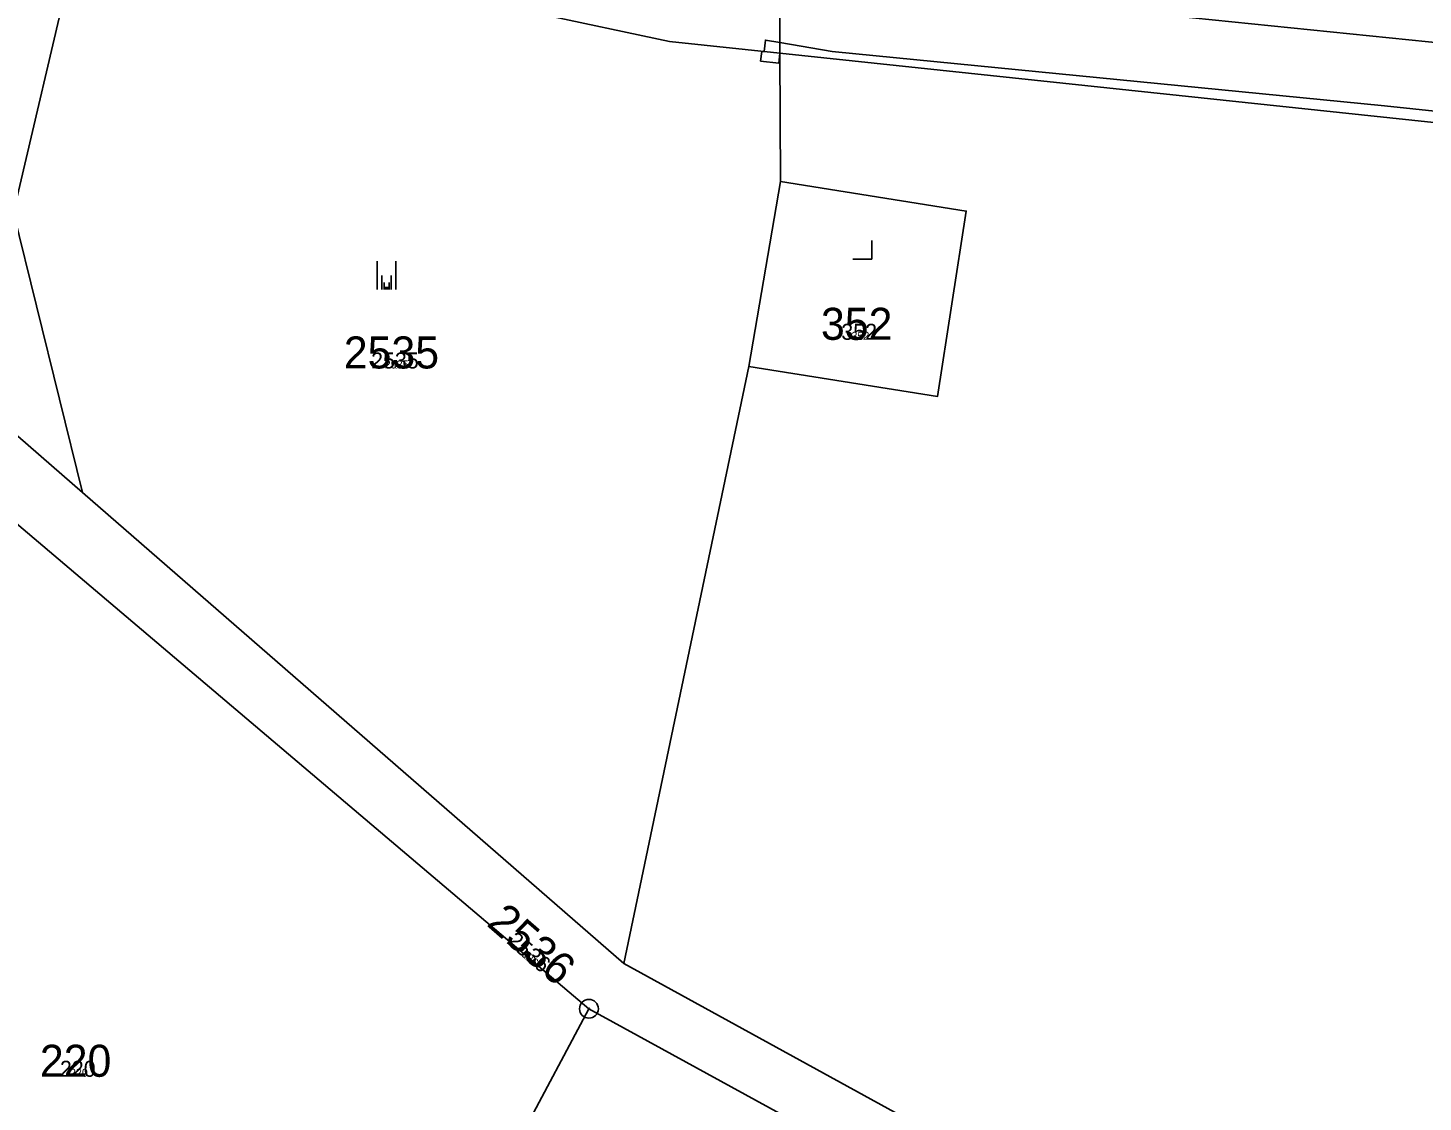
# Model space of a CAD drawing. Extents: x -744652 to -739090, y -980828 to -975855.
# Drawn here: x -742109.1 to -742035.1, y -978683 to -978626 of the extents above; entities that cross this region are included whole.
import ezdxf

# ---------------------------------------------------------------- set-up
doc = ezdxf.new("R2010")
doc.units = 0
for name, color, linetype in [('KAT_02_hranice parcel', 7, 'Continuous'), ('KAT_03_1000_st čísla parcelní', 7, 'Continuous'), ('KAT_03_1000_čísla parcelní', 7, 'Continuous'), ('KAT_03_1000_čísla popisná', 7, 'Continuous'), ('KAT_03_100_st čísla parcelní', 7, 'Continuous'), ('KAT_03_100_čísla parcelní', 7, 'Continuous'), ('KAT_03_100_čísla popisná', 7, 'Continuous'), ('KAT_03_250_st čísla parcelní', 7, 'Continuous'), ('KAT_03_250_čísla parcelní', 7, 'Continuous'), ('KAT_03_250_čísla popisná', 7, 'Continuous'), ('KAT_03_500_st čísla parcelní', 7, 'Continuous'), ('KAT_03_500_čísla parcelní', 7, 'Continuous'), ('KAT_03_500_čísla popisná', 7, 'Continuous'), ('KAT_05_1000_značky kultur', 7, 'Continuous'), ('KAT_05_100_značky kultur', 7, 'Continuous'), ('KAT_05_250_značky kultur', 7, 'Continuous'), ('KAT_05_500_značky kultur', 7, 'Continuous'), ('KAT_10_věcná břemena', 7, 'Continuous'), ('KAT_11_značky bodu BP', 7, 'Continuous')]:
    doc.layers.add(name, color=color, linetype=linetype)

msp = doc.modelspace()

# ---------------------------------------------------------------- linework, layer by layer
at = {"layer": 'KAT_02_hranice parcel'}
for p, q in [((-742069.22, -978623.18), (-742069.2, -978627.31)), ((-742069.2, -978627.31), (-742069.17, -978634.11)), ((-742069.17, -978634.11), (-742070.85, -978643.93)), ((-742070.85, -978643.93), (-742077.49, -978675.61)), ((-742106.24, -978650.63), (-742113.14, -978644.63)), ((-742079.34, -978678.02), (-742116.55, -978646.51)), ((-742077.49, -978675.61), (-742106.24, -978650.63)), ((-742093.71, -978704.96), (-742079.34, -978678.02)), ((-742067.92, -978684.29), (-742079.34, -978678.02))]:
    msp.add_line(p, q, dxfattribs=at)
for points in [[(-742069.2, -978627.31), (-742075.06, -978626.69), (-742103.02, -978620.72), (-742106.79, -978622.55)], [(-742106.24, -978650.63), (-742109.89, -978635.76), (-742106.79, -978622.55)], [(-742069.22, -978623.18), (-742028.5, -978627.35), (-741981.79, -978633.75), (-741962.38, -978634.82)], [(-741962.75, -978639.16), (-741982.64, -978638.06), (-742028.31, -978631.64), (-742069.2, -978627.31)], [(-742070.85, -978643.93), (-742060.84, -978645.53), (-742059.31, -978635.69), (-742069.17, -978634.11)], [(-742043.05, -978697.9), (-742041.51, -978695.1), (-742054.13, -978688.45), (-742077.49, -978675.61)]]:
    msp.add_lwpolyline(points, dxfattribs=at)
at = {"layer": 'KAT_05_1000_značky kultur'}
for p, q in [((-742064.33, -978638.24), (-742064.33, -978637.24)), ((-742090.591, -978639.85), (-742090.591, -978638.35)), ((-742089.59, -978639.85), (-742089.59, -978638.35)), ((-742065.331, -978638.24), (-742064.33, -978638.24))]:
    msp.add_line(p, q, dxfattribs=at)
at = {"layer": 'KAT_05_100_značky kultur'}
for p, q in [((-742064.43, -978638.24), (-742064.33, -978638.24)), ((-742064.33, -978638.24), (-742064.33, -978638.14)), ((-742090.131, -978639.85), (-742090.131, -978639.7)), ((-742090.031, -978639.85), (-742090.031, -978639.7))]:
    msp.add_line(p, q, dxfattribs=at)
at = {"layer": 'KAT_05_250_značky kultur'}
for p, q in [((-742064.33, -978638.24), (-742064.33, -978637.99)), ((-742064.58, -978638.24), (-742064.33, -978638.24)), ((-742090.208, -978639.85), (-742090.208, -978639.475)), ((-742089.958, -978639.85), (-742089.958, -978639.475))]:
    msp.add_line(p, q, dxfattribs=at)
at = {"layer": 'KAT_05_500_značky kultur'}
for p, q in [((-742064.33, -978638.24), (-742064.33, -978637.74)), ((-742064.831, -978638.24), (-742064.33, -978638.24)), ((-742090.336, -978639.85), (-742090.336, -978639.1)), ((-742089.835, -978639.85), (-742089.835, -978639.1))]:
    msp.add_line(p, q, dxfattribs=at)
at = {"layer": 'KAT_10_věcná břemena'}
msp.add_lwpolyline([(-742020.9, -978631.81), (-742037.11, -978630.1), (-742066.43, -978627.21), (-742069.2, -978626.74), (-742069.97, -978626.61), (-742070.04, -978627.22), (-742069.2, -978627.31), (-742028.31, -978631.64)], dxfattribs=at)
msp.add_lwpolyline([(-742069.26, -978627.84), (-742069.2, -978627.31), (-742070.04, -978627.22), (-742070.17, -978627.21), (-742070.23, -978627.73)], close=True, dxfattribs=at)
at = {"layer": 'KAT_11_značky bodu BP'}
for radius in [0.5, 0.0303]:
    msp.add_circle((-742079.34, -978678.02), radius, dxfattribs=at)

# ---------------------------------------------------------------- texts
at = {"layer": 'KAT_03_1000_st čísla parcelní'}
msp.add_text('352', height=1.7, dxfattribs=at).set_placement((-742067.024, -978642.52))
at = {"layer": 'KAT_03_1000_čísla parcelní'}
for s, p in [('2535', (-742092.357, -978644.04)), ('220', (-742108.494, -978681.63))]:
    msp.add_text(s, height=1.7, dxfattribs=at).set_placement(p)
msp.add_text('2536', height=1.7, rotation=319, dxfattribs=at).set_placement((-742084.829, -978673.566))
at = {"layer": 'KAT_03_1000_čísla popisná'}
msp.add_text('352', height=0.017, dxfattribs=at).set_placement((-742064.884, -978642.52))
at = {"layer": 'KAT_03_100_st čísla parcelní'}
msp.add_text('352', height=0.17, dxfattribs=at).set_placement((-742065.078, -978642.52))
at = {"layer": 'KAT_03_100_čísla parcelní'}
for s, p in [('2535', (-742089.749, -978644.04)), ('220', (-742106.579, -978681.63))]:
    msp.add_text(s, height=0.17, dxfattribs=at).set_placement(p)
msp.add_text('2536', height=0.17, rotation=319, dxfattribs=at).set_placement((-742082.892, -978675.249))
at = {"layer": 'KAT_03_100_čísla popisná'}
msp.add_text('352', height=0.0017, dxfattribs=at).set_placement((-742064.864, -978642.52))
at = {"layer": 'KAT_03_250_st čísla parcelní'}
msp.add_text('352', height=0.425, dxfattribs=at).set_placement((-742065.403, -978642.52))
at = {"layer": 'KAT_03_250_čísla parcelní'}
for s, p in [('2535', (-742090.184, -978644.04)), ('220', (-742106.898, -978681.63))]:
    msp.add_text(s, height=0.425, dxfattribs=at).set_placement(p)
msp.add_text('2536', height=0.425, rotation=319, dxfattribs=at).set_placement((-742083.215, -978674.969))
at = {"layer": 'KAT_03_250_čísla popisná'}
msp.add_text('352', height=0.00425, dxfattribs=at).set_placement((-742064.868, -978642.52))
at = {"layer": 'KAT_03_500_st čísla parcelní'}
msp.add_text('352', height=0.85, dxfattribs=at).set_placement((-742065.943, -978642.52))
at = {"layer": 'KAT_03_500_čísla parcelní'}
for s, p in [('2535', (-742090.908, -978644.04)), ('220', (-742107.43, -978681.63))]:
    msp.add_text(s, height=0.85, dxfattribs=at).set_placement(p)
msp.add_text('2536', height=0.85, rotation=319, dxfattribs=at).set_placement((-742083.753, -978674.501))
at = {"layer": 'KAT_03_500_čísla popisná'}
msp.add_text('352', height=0.0085, dxfattribs=at).set_placement((-742064.873, -978642.52))

doc.saveas('drawing.dxf')
